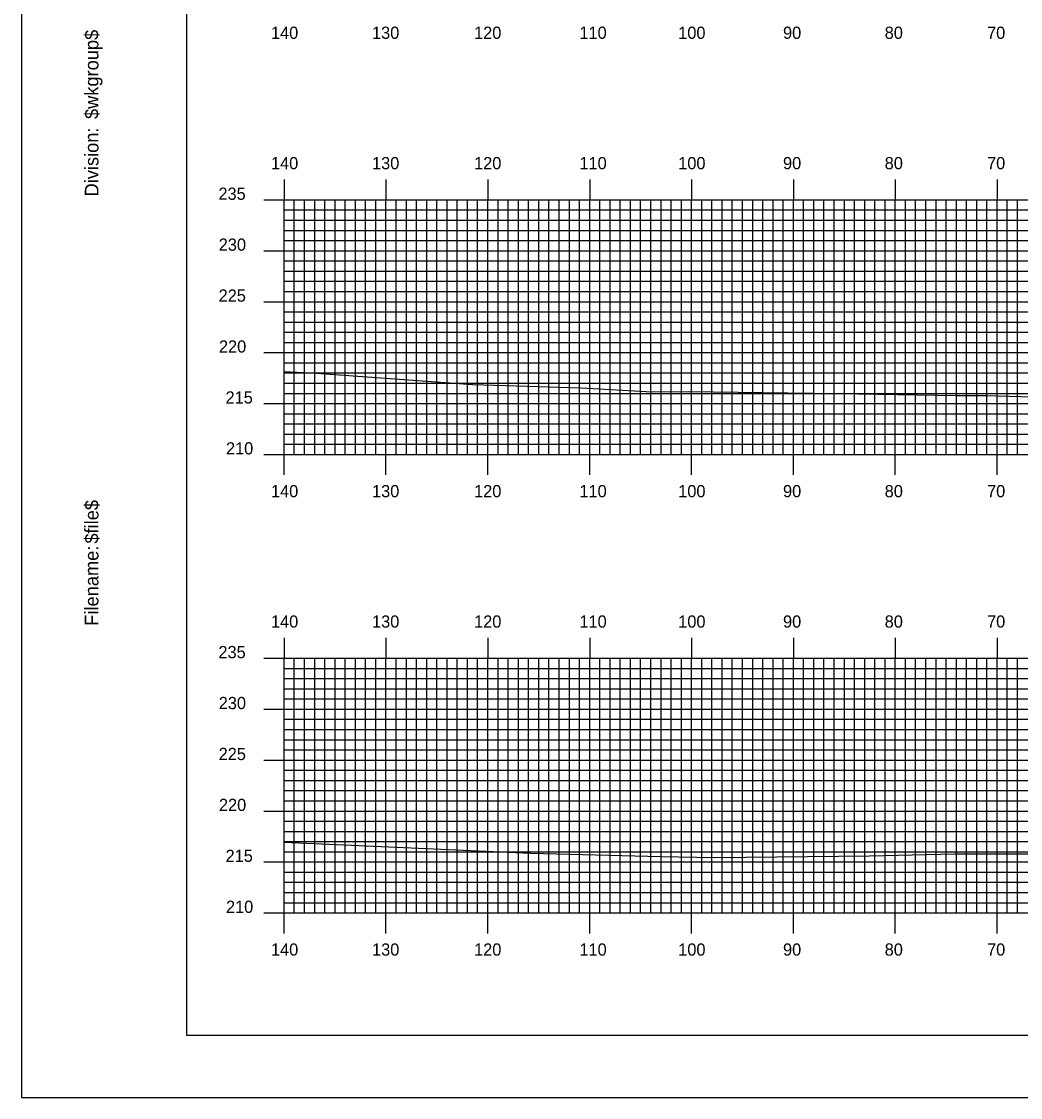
# Model space of a CAD drawing. Extents: x 1819244 to 1819587, y 442591 to 442811.
# Drawn here: x 1819243.9 to 1819342, y 442590.5 to 442696.2 of the extents above; entities that cross this region are included whole.
import ezdxf

# ---------------------------------------------------------------- set-up
doc = ezdxf.new("R2010")
doc.units = 0
for name, color, linetype in [('BORDER', 7, 'Continuous'), ('H_V ANNOTATION', 7, 'Continuous'), ('MAJOR', 7, 'Continuous'), ('MINOR', 7, 'Continuous'), ('PLOT BOUNDARY', 7, 'Continuous'), ('S_Roadway_Centerline', 7, 'Continuous')]:
    doc.layers.add(name, color=color, linetype=linetype)

msp = doc.modelspace()

# ---------------------------------------------------------------- linework, layer by layer
at = {"layer": 'BORDER'}
msp.add_lwpolyline([(1819260.06, 442596.67), (1819580.06, 442596.67), (1819580.06, 442806.67), (1819260.06, 442806.67)], close=True, dxfattribs=at)
at = {"layer": 'MAJOR'}
for p, q in [((1819269.66, 442680.67), (1819269.66, 442678.67)), ((1819279.66, 442680.67), (1819279.66, 442678.67)), ((1819289.66, 442680.67), (1819289.66, 442678.67)), ((1819299.66, 442680.67), (1819299.66, 442678.67)), ((1819309.66, 442680.67), (1819309.66, 442678.67)), ((1819319.66, 442680.67), (1819319.66, 442678.67)), ((1819329.66, 442680.67), (1819329.66, 442678.67)), ((1819339.66, 442680.67), (1819339.66, 442678.67)), ((1819267.66, 442678.67), (1819269.66, 442678.67)), ((1819269.66, 442678.67), (1819549.66, 442678.67)), ((1819269.66, 442653.67), (1819269.66, 442678.67)), ((1819269.66, 442653.67), (1819269.66, 442678.67)), ((1819269.66, 442678.67), (1819549.66, 442678.67)), ((1819279.66, 442653.67), (1819279.66, 442678.67)), ((1819289.66, 442653.67), (1819289.66, 442678.67)), ((1819299.66, 442653.67), (1819299.66, 442678.67)), ((1819309.66, 442653.67), (1819309.66, 442678.67)), ((1819319.66, 442653.67), (1819319.66, 442678.67)), ((1819329.66, 442653.67), (1819329.66, 442678.67)), ((1819339.66, 442653.67), (1819339.66, 442678.67)), ((1819267.66, 442673.67), (1819269.66, 442673.67)), ((1819269.66, 442673.67), (1819549.66, 442673.67)), ((1819267.66, 442668.67), (1819269.66, 442668.67)), ((1819269.66, 442668.67), (1819549.66, 442668.67)), ((1819267.66, 442663.67), (1819269.66, 442663.67)), ((1819269.66, 442663.67), (1819549.66, 442663.67)), ((1819267.66, 442658.67), (1819269.66, 442658.67)), ((1819269.66, 442658.67), (1819549.66, 442658.67)), ((1819267.66, 442653.67), (1819269.66, 442653.67)), ((1819269.66, 442653.67), (1819549.66, 442653.67)), ((1819269.66, 442653.67), (1819549.66, 442653.67)), ((1819269.66, 442651.66), (1819269.66, 442653.67)), ((1819279.66, 442651.66), (1819279.66, 442653.67)), ((1819289.66, 442651.66), (1819289.66, 442653.67)), ((1819299.66, 442651.66), (1819299.66, 442653.67)), ((1819309.66, 442651.66), (1819309.66, 442653.67)), ((1819319.66, 442651.66), (1819319.66, 442653.67)), ((1819329.66, 442651.66), (1819329.66, 442653.67)), ((1819339.66, 442651.66), (1819339.66, 442653.67)), ((1819269.66, 442635.67), (1819269.66, 442633.67)), ((1819279.66, 442635.67), (1819279.66, 442633.67)), ((1819289.66, 442635.67), (1819289.66, 442633.67)), ((1819299.66, 442635.67), (1819299.66, 442633.67)), ((1819309.66, 442635.67), (1819309.66, 442633.67)), ((1819319.66, 442635.67), (1819319.66, 442633.67)), ((1819329.66, 442635.67), (1819329.66, 442633.67)), ((1819339.66, 442635.67), (1819339.66, 442633.67)), ((1819267.66, 442633.67), (1819269.66, 442633.67)), ((1819269.66, 442633.67), (1819549.66, 442633.67)), ((1819269.66, 442608.67), (1819269.66, 442633.67)), ((1819269.66, 442608.67), (1819269.66, 442633.67)), ((1819269.66, 442633.67), (1819549.66, 442633.67)), ((1819279.66, 442608.67), (1819279.66, 442633.67)), ((1819289.66, 442608.67), (1819289.66, 442633.67)), ((1819299.66, 442608.67), (1819299.66, 442633.67)), ((1819309.66, 442608.67), (1819309.66, 442633.67)), ((1819319.66, 442608.67), (1819319.66, 442633.67)), ((1819329.66, 442608.67), (1819329.66, 442633.67)), ((1819339.66, 442608.67), (1819339.66, 442633.67)), ((1819267.66, 442628.67), (1819269.66, 442628.67)), ((1819269.66, 442628.67), (1819549.66, 442628.67)), ((1819267.66, 442623.67), (1819269.66, 442623.67)), ((1819269.66, 442623.67), (1819549.66, 442623.67)), ((1819267.66, 442618.67), (1819269.66, 442618.67)), ((1819269.66, 442618.67), (1819549.66, 442618.67)), ((1819267.66, 442613.67), (1819269.66, 442613.67)), ((1819269.66, 442613.67), (1819549.66, 442613.67)), ((1819267.66, 442608.67), (1819269.66, 442608.67)), ((1819269.66, 442608.67), (1819549.66, 442608.67)), ((1819269.66, 442608.67), (1819549.66, 442608.67)), ((1819269.66, 442606.66), (1819269.66, 442608.67)), ((1819279.66, 442606.66), (1819279.66, 442608.67)), ((1819289.66, 442606.66), (1819289.66, 442608.67)), ((1819299.66, 442606.66), (1819299.66, 442608.67)), ((1819309.66, 442606.66), (1819309.66, 442608.67)), ((1819319.66, 442606.66), (1819319.66, 442608.67)), ((1819329.66, 442606.66), (1819329.66, 442608.67)), ((1819339.66, 442606.66), (1819339.66, 442608.67))]:
    msp.add_line(p, q, dxfattribs=at)
at = {"layer": 'MINOR'}
for p, q in [((1819270.66, 442653.67), (1819270.66, 442678.67)), ((1819271.66, 442653.67), (1819271.66, 442678.67)), ((1819272.66, 442653.67), (1819272.66, 442678.67)), ((1819273.66, 442653.67), (1819273.66, 442678.67)), ((1819274.66, 442653.67), (1819274.66, 442678.67)), ((1819275.66, 442653.67), (1819275.66, 442678.67)), ((1819276.66, 442653.67), (1819276.66, 442678.67)), ((1819277.66, 442653.67), (1819277.66, 442678.67)), ((1819278.66, 442653.67), (1819278.66, 442678.67)), ((1819280.66, 442653.67), (1819280.66, 442678.67)), ((1819281.66, 442653.67), (1819281.66, 442678.67)), ((1819282.66, 442653.67), (1819282.66, 442678.67)), ((1819283.66, 442653.67), (1819283.66, 442678.67)), ((1819284.66, 442653.67), (1819284.66, 442678.67)), ((1819285.66, 442653.67), (1819285.66, 442678.67)), ((1819286.66, 442653.67), (1819286.66, 442678.67)), ((1819287.66, 442653.67), (1819287.66, 442678.67)), ((1819288.66, 442653.67), (1819288.66, 442678.67)), ((1819290.66, 442653.67), (1819290.66, 442678.67)), ((1819291.66, 442653.67), (1819291.66, 442678.67)), ((1819292.66, 442653.67), (1819292.66, 442678.67)), ((1819293.66, 442653.67), (1819293.66, 442678.67)), ((1819294.66, 442653.67), (1819294.66, 442678.67)), ((1819295.66, 442653.67), (1819295.66, 442678.67)), ((1819296.66, 442653.67), (1819296.66, 442678.67)), ((1819297.66, 442653.67), (1819297.66, 442678.67)), ((1819298.66, 442653.67), (1819298.66, 442678.67)), ((1819300.66, 442653.67), (1819300.66, 442678.67)), ((1819301.66, 442653.67), (1819301.66, 442678.67)), ((1819302.66, 442653.67), (1819302.66, 442678.67)), ((1819303.66, 442653.67), (1819303.66, 442678.67)), ((1819304.66, 442653.67), (1819304.66, 442678.67)), ((1819305.66, 442653.67), (1819305.66, 442678.67)), ((1819306.66, 442653.67), (1819306.66, 442678.67)), ((1819307.66, 442653.67), (1819307.66, 442678.67)), ((1819308.66, 442653.67), (1819308.66, 442678.67)), ((1819310.66, 442653.67), (1819310.66, 442678.67)), ((1819311.66, 442653.67), (1819311.66, 442678.67)), ((1819312.66, 442653.67), (1819312.66, 442678.67)), ((1819313.66, 442653.67), (1819313.66, 442678.67)), ((1819314.66, 442653.67), (1819314.66, 442678.67)), ((1819315.66, 442653.67), (1819315.66, 442678.67)), ((1819316.66, 442653.67), (1819316.66, 442678.67)), ((1819317.66, 442653.67), (1819317.66, 442678.67)), ((1819318.66, 442653.67), (1819318.66, 442678.67)), ((1819320.66, 442653.67), (1819320.66, 442678.67)), ((1819321.66, 442653.67), (1819321.66, 442678.67)), ((1819322.66, 442653.67), (1819322.66, 442678.67)), ((1819323.66, 442653.67), (1819323.66, 442678.67)), ((1819324.66, 442653.67), (1819324.66, 442678.67)), ((1819325.66, 442653.67), (1819325.66, 442678.67)), ((1819326.66, 442653.67), (1819326.66, 442678.67)), ((1819327.66, 442653.67), (1819327.66, 442678.67)), ((1819328.66, 442653.67), (1819328.66, 442678.67)), ((1819330.66, 442653.67), (1819330.66, 442678.67)), ((1819331.66, 442653.67), (1819331.66, 442678.67)), ((1819332.66, 442653.67), (1819332.66, 442678.67)), ((1819333.66, 442653.67), (1819333.66, 442678.67)), ((1819334.66, 442653.67), (1819334.66, 442678.67)), ((1819335.66, 442653.67), (1819335.66, 442678.67)), ((1819336.66, 442653.67), (1819336.66, 442678.67)), ((1819337.66, 442653.67), (1819337.66, 442678.67)), ((1819338.66, 442653.67), (1819338.66, 442678.67)), ((1819340.66, 442653.67), (1819340.66, 442678.67)), ((1819341.66, 442653.67), (1819341.66, 442678.67)), ((1819269.66, 442677.67), (1819549.66, 442677.67)), ((1819269.66, 442677.67), (1819271.67, 442677.67)), ((1819269.66, 442676.67), (1819549.66, 442676.67)), ((1819269.66, 442676.67), (1819271.67, 442676.67)), ((1819269.66, 442675.67), (1819549.66, 442675.67)), ((1819269.66, 442675.67), (1819271.67, 442675.67)), ((1819269.66, 442674.67), (1819549.66, 442674.67)), ((1819269.66, 442674.67), (1819271.67, 442674.67)), ((1819269.66, 442672.67), (1819549.66, 442672.67)), ((1819269.66, 442672.67), (1819271.67, 442672.67)), ((1819269.66, 442671.67), (1819549.66, 442671.67)), ((1819269.66, 442671.67), (1819271.67, 442671.67)), ((1819269.66, 442670.67), (1819549.66, 442670.67)), ((1819269.66, 442670.67), (1819271.67, 442670.67)), ((1819269.66, 442669.67), (1819549.66, 442669.67)), ((1819269.66, 442669.67), (1819271.67, 442669.67)), ((1819269.66, 442667.67), (1819549.66, 442667.67)), ((1819269.66, 442667.67), (1819271.67, 442667.67)), ((1819269.66, 442666.67), (1819549.66, 442666.67)), ((1819269.66, 442666.67), (1819271.67, 442666.67)), ((1819269.66, 442665.67), (1819549.66, 442665.67)), ((1819269.66, 442665.67), (1819271.67, 442665.67)), ((1819269.66, 442664.67), (1819549.66, 442664.67)), ((1819269.66, 442664.67), (1819271.67, 442664.67)), ((1819269.66, 442662.67), (1819549.66, 442662.67)), ((1819269.66, 442662.67), (1819271.67, 442662.67)), ((1819269.66, 442661.67), (1819549.66, 442661.67)), ((1819269.66, 442661.67), (1819271.67, 442661.67)), ((1819269.66, 442660.67), (1819549.66, 442660.67)), ((1819269.66, 442660.67), (1819271.67, 442660.67)), ((1819269.66, 442659.67), (1819549.66, 442659.67)), ((1819269.66, 442659.67), (1819271.67, 442659.67)), ((1819269.66, 442657.67), (1819549.66, 442657.67)), ((1819269.66, 442657.67), (1819271.67, 442657.67)), ((1819269.66, 442656.67), (1819549.66, 442656.67)), ((1819269.66, 442656.67), (1819271.67, 442656.67)), ((1819269.66, 442655.67), (1819549.66, 442655.67)), ((1819269.66, 442655.67), (1819271.67, 442655.67)), ((1819269.66, 442654.67), (1819549.66, 442654.67)), ((1819269.66, 442654.67), (1819271.67, 442654.67)), ((1819270.66, 442608.67), (1819270.66, 442633.67)), ((1819271.66, 442608.67), (1819271.66, 442633.67)), ((1819272.66, 442608.67), (1819272.66, 442633.67)), ((1819273.66, 442608.67), (1819273.66, 442633.67)), ((1819274.66, 442608.67), (1819274.66, 442633.67)), ((1819275.66, 442608.67), (1819275.66, 442633.67)), ((1819276.66, 442608.67), (1819276.66, 442633.67)), ((1819277.66, 442608.67), (1819277.66, 442633.67)), ((1819278.66, 442608.67), (1819278.66, 442633.67)), ((1819280.66, 442608.67), (1819280.66, 442633.67)), ((1819281.66, 442608.67), (1819281.66, 442633.67)), ((1819282.66, 442608.67), (1819282.66, 442633.67)), ((1819283.66, 442608.67), (1819283.66, 442633.67)), ((1819284.66, 442608.67), (1819284.66, 442633.67)), ((1819285.66, 442608.67), (1819285.66, 442633.67)), ((1819286.66, 442608.67), (1819286.66, 442633.67)), ((1819287.66, 442608.67), (1819287.66, 442633.67)), ((1819288.66, 442608.67), (1819288.66, 442633.67)), ((1819290.66, 442608.67), (1819290.66, 442633.67)), ((1819291.66, 442608.67), (1819291.66, 442633.67)), ((1819292.66, 442608.67), (1819292.66, 442633.67)), ((1819293.66, 442608.67), (1819293.66, 442633.67)), ((1819294.66, 442608.67), (1819294.66, 442633.67)), ((1819295.66, 442608.67), (1819295.66, 442633.67)), ((1819296.66, 442608.67), (1819296.66, 442633.67)), ((1819297.66, 442608.67), (1819297.66, 442633.67)), ((1819298.66, 442608.67), (1819298.66, 442633.67)), ((1819300.66, 442608.67), (1819300.66, 442633.67)), ((1819301.66, 442608.67), (1819301.66, 442633.67)), ((1819302.66, 442608.67), (1819302.66, 442633.67)), ((1819303.66, 442608.67), (1819303.66, 442633.67)), ((1819304.66, 442608.67), (1819304.66, 442633.67)), ((1819305.66, 442608.67), (1819305.66, 442633.67)), ((1819306.66, 442608.67), (1819306.66, 442633.67)), ((1819307.66, 442608.67), (1819307.66, 442633.67)), ((1819308.66, 442608.67), (1819308.66, 442633.67)), ((1819310.66, 442608.67), (1819310.66, 442633.67)), ((1819311.66, 442608.67), (1819311.66, 442633.67)), ((1819312.66, 442608.67), (1819312.66, 442633.67)), ((1819313.66, 442608.67), (1819313.66, 442633.67)), ((1819314.66, 442608.67), (1819314.66, 442633.67)), ((1819315.66, 442608.67), (1819315.66, 442633.67)), ((1819316.66, 442608.67), (1819316.66, 442633.67)), ((1819317.66, 442608.67), (1819317.66, 442633.67)), ((1819318.66, 442608.67), (1819318.66, 442633.67)), ((1819320.66, 442608.67), (1819320.66, 442633.67)), ((1819321.66, 442608.67), (1819321.66, 442633.67)), ((1819322.66, 442608.67), (1819322.66, 442633.67)), ((1819323.66, 442608.67), (1819323.66, 442633.67)), ((1819324.66, 442608.67), (1819324.66, 442633.67)), ((1819325.66, 442608.67), (1819325.66, 442633.67)), ((1819326.66, 442608.67), (1819326.66, 442633.67)), ((1819327.66, 442608.67), (1819327.66, 442633.67)), ((1819328.66, 442608.67), (1819328.66, 442633.67)), ((1819330.66, 442608.67), (1819330.66, 442633.67)), ((1819331.66, 442608.67), (1819331.66, 442633.67)), ((1819332.66, 442608.67), (1819332.66, 442633.67)), ((1819333.66, 442608.67), (1819333.66, 442633.67)), ((1819334.66, 442608.67), (1819334.66, 442633.67)), ((1819335.66, 442608.67), (1819335.66, 442633.67)), ((1819336.66, 442608.67), (1819336.66, 442633.67)), ((1819337.66, 442608.67), (1819337.66, 442633.67)), ((1819338.66, 442608.67), (1819338.66, 442633.67)), ((1819340.66, 442608.67), (1819340.66, 442633.67)), ((1819341.66, 442608.67), (1819341.66, 442633.67)), ((1819269.66, 442632.67), (1819549.66, 442632.67)), ((1819269.66, 442632.67), (1819271.67, 442632.67)), ((1819269.66, 442631.67), (1819549.66, 442631.67)), ((1819269.66, 442631.67), (1819271.67, 442631.67)), ((1819269.66, 442630.67), (1819549.66, 442630.67)), ((1819269.66, 442630.67), (1819271.67, 442630.67)), ((1819269.66, 442629.67), (1819549.66, 442629.67)), ((1819269.66, 442629.67), (1819271.67, 442629.67)), ((1819269.66, 442627.67), (1819549.66, 442627.67)), ((1819269.66, 442627.67), (1819271.67, 442627.67)), ((1819269.66, 442626.67), (1819549.66, 442626.67)), ((1819269.66, 442626.67), (1819271.67, 442626.67)), ((1819269.66, 442625.67), (1819549.66, 442625.67)), ((1819269.66, 442625.67), (1819271.67, 442625.67)), ((1819269.66, 442624.67), (1819549.66, 442624.67)), ((1819269.66, 442624.67), (1819271.67, 442624.67)), ((1819269.66, 442622.67), (1819549.66, 442622.67)), ((1819269.66, 442622.67), (1819271.67, 442622.67)), ((1819269.66, 442621.67), (1819549.66, 442621.67)), ((1819269.66, 442621.67), (1819271.67, 442621.67)), ((1819269.66, 442620.67), (1819549.66, 442620.67)), ((1819269.66, 442620.67), (1819271.67, 442620.67)), ((1819269.66, 442619.67), (1819549.66, 442619.67)), ((1819269.66, 442619.67), (1819271.67, 442619.67)), ((1819269.66, 442617.67), (1819549.66, 442617.67)), ((1819269.66, 442617.67), (1819271.67, 442617.67)), ((1819269.66, 442616.67), (1819549.66, 442616.67)), ((1819269.66, 442616.67), (1819271.67, 442616.67)), ((1819269.66, 442615.67), (1819549.66, 442615.67)), ((1819269.66, 442615.67), (1819271.67, 442615.67)), ((1819269.66, 442614.67), (1819549.66, 442614.67)), ((1819269.66, 442614.67), (1819271.67, 442614.67)), ((1819269.66, 442612.67), (1819549.66, 442612.67)), ((1819269.66, 442612.67), (1819271.67, 442612.67)), ((1819269.66, 442611.67), (1819549.66, 442611.67)), ((1819269.66, 442611.67), (1819271.67, 442611.67)), ((1819269.66, 442610.67), (1819549.66, 442610.67)), ((1819269.66, 442610.67), (1819271.67, 442610.67)), ((1819269.66, 442609.67), (1819549.66, 442609.67)), ((1819269.66, 442609.67), (1819271.67, 442609.67))]:
    msp.add_line(p, q, dxfattribs=at)
at = {"layer": 'PLOT BOUNDARY'}
msp.add_lwpolyline([(1819243.88, 442590.55), (1819583.88, 442590.55), (1819583.88, 442810.55), (1819243.88, 442810.55)], close=True, dxfattribs=at)
at = {"layer": 'S_Roadway_Centerline'}
for points in [[(1819269.66, 442661.81), (1819272.84, 442661.65), (1819288.18, 442660.54), (1819298.83, 442660.21), (1819305.8, 442659.82), (1819309.32, 442659.84), (1819324.02, 442659.64), (1819335.7, 442659.47), (1819338.56, 442659.45), (1819349.95, 442659.12), (1819367.28, 442659.03), (1819373.27, 442659.05), (1819375.37, 442659.05), (1819379.12, 442659.02), (1819389.34, 442659.05), (1819399.59, 442659.04), (1819406.62, 442659.2), (1819413.61, 442659.43), (1819427.62, 442659.95), (1819441.07, 442659.6), (1819445.92, 442659.51), (1819453.66, 442659.34), (1819475.45, 442659.08)], [(1819269.66, 442615.62), (1819293.86, 442614.52), (1819306.64, 442614.2), (1819311.94, 442614.11), (1819327.13, 442614.27), (1819335.51, 442614.45), (1819347.42, 442614.45), (1819360.58, 442614.34), (1819366.06, 442614.56), (1819375.69, 442614.38), (1819387.59, 442614.82), (1819390.43, 442614.85), (1819412.09, 442614.91), (1819428.46, 442614.6), (1819437.12, 442614.23), (1819454.08, 442614.33), (1819455.16, 442614.33), (1819459.08, 442614.33), (1819469.49, 442614.31), (1819471.65, 442614.4)]]:
    msp.add_lwpolyline(points, dxfattribs=at)

# ---------------------------------------------------------------- texts
at = {"layer": 'BORDER'}
for s, p in [('$wkgroup$', (1819251.43, 442686.6)), ('Division:', (1819251.43, 442679)), ('$file$', (1819251.43, 442644.92)), ('Filename:', (1819251.43, 442636.86))]:
    msp.add_text(s, height=1.339, rotation=90, dxfattribs=at).set_placement(p)
at = {"layer": 'H_V ANNOTATION'}
for s, p in [('140', (1819268.37, 442694.47)), ('130', (1819278.29, 442694.47)), ('120', (1819288.31, 442694.47)), ('110', (1819298.65, 442694.47)), ('100', (1819308.35, 442694.47)), ('90', (1819318.64, 442694.47)), ('80', (1819328.62, 442694.47)), ('70', (1819338.67, 442694.47)), ('140', (1819268.37, 442681.67)), ('130', (1819278.29, 442681.67)), ('120', (1819288.31, 442681.67)), ('110', (1819298.65, 442681.67)), ('100', (1819308.35, 442681.67)), ('90', (1819318.64, 442681.67)), ('80', (1819328.62, 442681.67)), ('70', (1819338.67, 442681.67)), ('235', (1819263.21, 442678.67)), ('230', (1819263.24, 442673.67)), ('225', (1819263.23, 442668.67)), ('220', (1819263.26, 442663.67)), ('215', (1819263.91, 442658.67)), ('210', (1819263.95, 442653.67)), ('140', (1819268.37, 442649.47)), ('130', (1819278.29, 442649.47)), ('120', (1819288.31, 442649.47)), ('110', (1819298.65, 442649.47)), ('100', (1819308.35, 442649.47)), ('90', (1819318.64, 442649.47)), ('80', (1819328.62, 442649.47)), ('70', (1819338.67, 442649.47)), ('140', (1819268.37, 442636.67)), ('130', (1819278.29, 442636.67)), ('120', (1819288.31, 442636.67)), ('110', (1819298.65, 442636.67)), ('100', (1819308.35, 442636.67)), ('90', (1819318.64, 442636.67)), ('80', (1819328.62, 442636.67)), ('70', (1819338.67, 442636.67)), ('235', (1819263.21, 442633.67)), ('230', (1819263.24, 442628.67)), ('225', (1819263.23, 442623.67)), ('220', (1819263.26, 442618.67)), ('215', (1819263.91, 442613.67)), ('210', (1819263.95, 442608.67)), ('140', (1819268.37, 442604.47)), ('130', (1819278.29, 442604.47)), ('120', (1819288.31, 442604.47)), ('110', (1819298.65, 442604.47)), ('100', (1819308.35, 442604.47)), ('90', (1819318.64, 442604.47)), ('80', (1819328.62, 442604.47)), ('70', (1819338.67, 442604.47))]:
    msp.add_text(s, height=1.2, dxfattribs=at).set_placement(p)
at = {"layer": 'MAJOR'}
for p in [(1819269.66, 442653.67), (1819269.66, 442608.67)]:
    msp.add_text('-', height=0.012, dxfattribs=at).set_placement(p)

doc.saveas('drawing.dxf')
